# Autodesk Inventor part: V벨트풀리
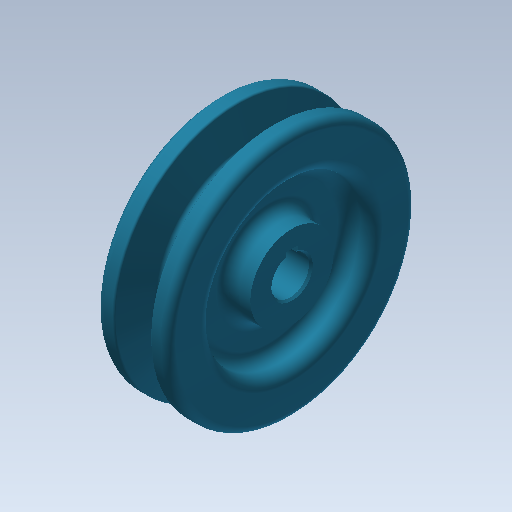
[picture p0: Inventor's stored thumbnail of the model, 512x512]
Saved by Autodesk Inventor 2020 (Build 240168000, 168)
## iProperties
Created: 2015-11
Part Number: V벨트풀리
Material: 강철, 탄소
Document SubType Name: Modeling
Designer: mduedu
Density: 1 g/cm^3
Appearance: 터키옥색
Author: mduedu
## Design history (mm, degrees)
sketch "스케치1"
  geometry: L1 (-9.5, 0)-(9.5, 0); L2 (0, 0)-(0, 32.7); L3 (-4.825, 32.7)-(-9.5, 32.7); L4 (-9.5, 32.7)-(-9.5, 0); L5 (0, 23.7)-(-2.074, 23.7); L6 (-2.074, 23.7)-(-4.825, 32.7); L7 (4.825, 32.7)-(9.5, 32.7); L8 (9.5, 32.7)-(9.5, 0); L9 (0, 23.7)-(2.074, 23.7); L10 (2.074, 23.7)-(4.825, 32.7); L11 (-9.5, 30)-(9.5, 30); 3 further points
  constraints: 22 end point, 7 point on line, 4 perpendicular, 3 symmetric about line, 1 coincident, 1 horizontal, 1 horizontal alignment, 1 midpoint, 1 vertical
  dimensions: "d0" = 19 distance of L1.start L1.end; "d2" = 65.4 diameter of L2.end L1 (derived); "d3" = 34 deg angle of L10 L6; "d4" = 6.3 distance between parallel lines of L11 L9; "d5" = 2.7 distance between parallel lines of L7 L11; "d6" = 8 distance of point (4, 30) point (-4, 30); "d7" = 60 diameter of L11 L1
revolve "회전1" sketch "스케치1" stored, may be unused: angle "d8" = 90 deg
sketch "스케치2"
  geometry: C1 r 21 at (0, 0); C2 r 11 at (0, 0); 1 further point
  constraints: 2 centre point, 2 coincident
  dimensions: "d9" = 42 diameter of C1; "d10" = 22 diameter of C2
extrude "돌출1" cut sketch "스케치2" distance "d11" = 6; taper "d12" = 0 deg
fillet "모깎기1" dims "d13" = 3
fillet "모깎기2" dims "d14" = 3
fillet "모깎기3" dims "d15" = 1, "d16" = 0.5, "d17" = 2
hole "구멍1" diameter "d20" = 10; stored, may be unused: countersink angle "d24" = 90 deg, drill point angle "d26" = 118 deg; dims "d18" = 10, "d19" = 10, "d21" = 6, "d22" = 4, "d23" = 2, "d25" = 8
sketch "스케치3"
  geometry: L1 (-1.5, 0)-(1.5, 0); L2 (1.5, 0)-(1.5, 6.4); L3 (1.5, 6.4)-(-1.5, 6.4); L4 (-1.5, 6.4)-(-1.5, 0); 2 further points
  constraints: 8 end point, 2 parallel, 1 coincident, 1 horizontal, 1 midpoint, 1 perpendicular
  dimensions: "d27" = 3 distance of L2.end L3.end; "d29" = 6.4 distance of L3.end L1.start
extrude "돌출2" cut sketch "스케치3" extent not by distance; stored distance "d30" = 6; taper "d31" = 0 deg
chamfer "모따기1" distance "d32" = 0.5; stored, may be unused: second distance "d33" = 2, angle "d34" = 45 deg
node "솔리드1"
mirror "대칭1"
